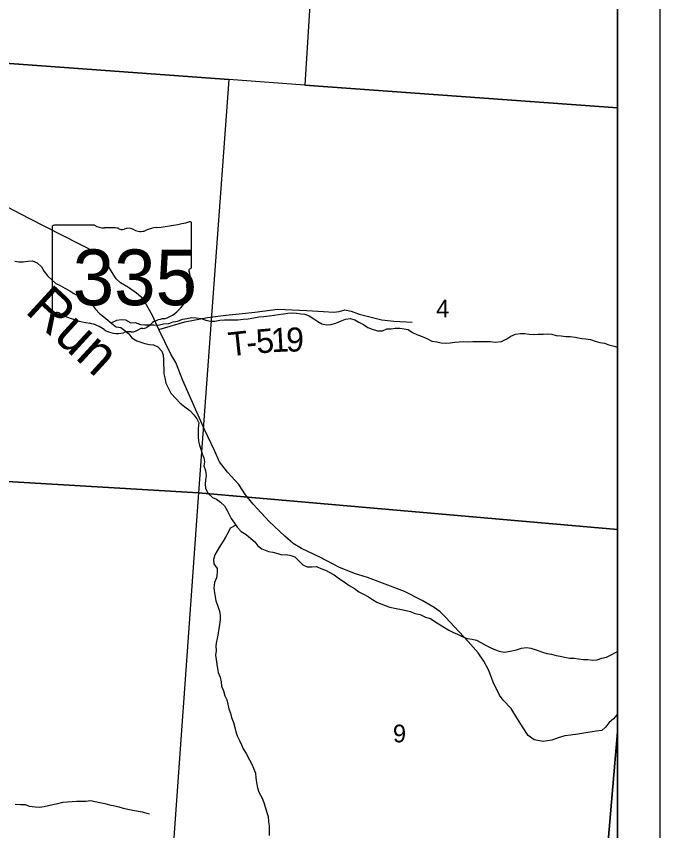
# Model space of a CAD drawing. Extents: x 0 to 34, y 0 to 22.
# Drawn here: x 29.394 to 30.917, y 15.21 to 17.138 of the extents above; entities that cross this region are included whole.
import ezdxf

# ---------------------------------------------------------------- set-up
doc = ezdxf.new("R2010")
doc.units = 0
for name, color, linetype in [('GM_X_County', 7, 'Continuous'), ('GM_X_Minor_River', 7, 'Continuous'), ('GM_X_Minor_River_Text', 7, 'Continuous'), ('GM_X_Section', 7, 'Continuous'), ('GM_X_Section_Text', 7, 'Continuous'), ('GM_X_State_Location', 7, 'Continuous'), ('GM_X_State_Route', 7, 'Continuous'), ('GM_X_State_Shield', 7, 'Continuous'), ('GM_X_Township', 7, 'Continuous'), ('GM_X_Township_Road', 7, 'Continuous'), ('GM_X_Township_Road_Text', 7, 'Continuous'), ('SH_Data', 7, 'Continuous')]:
    doc.layers.add(name, color=color, linetype=linetype)

msp = doc.modelspace()

# ---------------------------------------------------------------- linework, layer by layer
at = {"layer": 'GM_X_County'}
msp.add_lwpolyline([(24.0167, 20.4902), (24.0167, 14.1), (30.8167, 14.1), (30.8167, 19.9966)], dxfattribs=at)
at = {"layer": 'GM_X_Minor_River'}
for points in [[(29.3901, 16.5582), (29.3999, 16.5567), (29.4102, 16.5567), (29.4211, 16.5583), (29.4317, 16.559), (29.4431, 16.5541), (29.453, 16.5443), (29.4594, 16.5337), (29.4682, 16.5227), (29.4871, 16.5053), (29.4977, 16.5), (29.5084, 16.4943), (29.5205, 16.4879), (29.53, 16.4814), (29.5425, 16.4754), (29.552, 16.4686), (29.5626, 16.4621), (29.5736, 16.4538), (29.5808, 16.4443), (29.5903, 16.4341), (29.6005, 16.4265), (29.6104, 16.4186), (29.6199, 16.4102), (29.6301, 16.4023), (29.6407, 16.4008), (29.6502, 16.394), (29.66, 16.3856), (29.6673, 16.3762), (29.6786, 16.369), (29.6885, 16.3659), (29.698, 16.3633), (29.7086, 16.3607), (29.7184, 16.3599), (29.7286, 16.3554), (29.7378, 16.3448), (29.7416, 16.3353), (29.7423, 16.3251), (29.742, 16.314), (29.7428, 16.3023), (29.7432, 16.2913), (29.7451, 16.2818), (29.7474, 16.2693), (29.7531, 16.2579), (29.7595, 16.2454), (29.7713, 16.2329), (29.7808, 16.2223), (29.7926, 16.2132), (29.8047, 16.2041), (29.8142, 16.1943), (29.8206, 16.1848), (29.8256, 16.1753), (29.8245, 16.1624), (29.8245, 16.1423), (29.8253, 16.1321), (29.8276, 16.1226), (29.8306, 16.1131), (29.8337, 16.1021), (29.8379, 16.0926), (29.8394, 16.0828), (29.8375, 16.0733), (29.8413, 16.0623)], [(29.618, 16.4118), (29.6312, 16.4182), (29.6422, 16.4201), (29.652, 16.419), (29.6645, 16.4122), (29.6748, 16.4126), (29.6876, 16.4077), (29.6982, 16.4069), (29.7194, 16.407), (29.7293, 16.4066), (29.7418, 16.4097), (29.755, 16.4108), (29.7649, 16.4143), (29.7762, 16.4158), (29.7872, 16.4204), (29.7978, 16.4223), (29.8084, 16.4249), (29.8194, 16.4242), (29.8315, 16.4219), (29.8425, 16.4182), (29.8535, 16.4159), (29.8637, 16.4156), (29.8754, 16.4182), (29.8864, 16.419), (29.8966, 16.4194), (29.9072, 16.419), (29.9182, 16.4194), (29.9303, 16.4206), (29.9424, 16.4214), (29.9557, 16.4237), (29.9674, 16.4263), (29.9799, 16.4267), (29.992, 16.4287), (30.0037, 16.4302), (30.0143, 16.4317), (30.0265, 16.4329), (30.0367, 16.4352), (30.0469, 16.4356), (30.0571, 16.4352), (30.067, 16.4333), (30.0768, 16.4322), (30.087, 16.4284), (30.0977, 16.4216), (30.1071, 16.4152), (30.117, 16.4099), (30.1268, 16.4069), (30.1378, 16.408), (30.1503, 16.4115), (30.1613, 16.416), (30.173, 16.4206), (30.1851, 16.4221), (30.1946, 16.4191), (30.2048, 16.4138), (30.2158, 16.4081), (30.2257, 16.401), (30.2363, 16.3968), (30.2484, 16.3934), (30.2601, 16.3934), (30.2704, 16.398), (30.2806, 16.3976), (30.2908, 16.3995), (30.3014, 16.3996), (30.3116, 16.3981), (30.3215, 16.3966), (30.3313, 16.3894), (30.342, 16.3844), (30.3545, 16.3795), (30.3658, 16.3746), (30.3776, 16.3686), (30.3893, 16.3667), (30.3992, 16.3648), (30.409, 16.3637), (30.4207, 16.3648), (30.4313, 16.366), (30.4416, 16.3668), (30.4518, 16.3676), (30.4639, 16.3672), (30.4745, 16.368), (30.4855, 16.3676), (30.5037, 16.368), (30.5165, 16.3677), (30.5268, 16.3665), (30.5419, 16.3681), (30.5544, 16.3738), (30.5642, 16.3806), (30.5756, 16.3852), (30.5869, 16.3871), (30.5975, 16.3864), (30.6074, 16.3853), (30.6183, 16.3841), (30.6293, 16.3849), (30.6411, 16.3849), (30.6513, 16.3857), (30.6611, 16.385), (30.6714, 16.3823), (30.6835, 16.3816), (30.6948, 16.3797), (30.7047, 16.3793), (30.7168, 16.3782), (30.732, 16.3752), (30.7418, 16.3741)], [(30.7418, 16.3741), (30.7532, 16.3722), (30.7638, 16.3684), (30.7748, 16.3658), (30.7857, 16.3635), (30.796, 16.3598), (30.8092, 16.3571), (30.8167, 16.3545)], [(29.8413, 16.0623), (29.8429, 16.0501), (29.8418, 16.0403), (29.8407, 16.0304), (29.8414, 16.0205), (29.8471, 16.0088), (29.8578, 15.9989), (29.8676, 15.9944), (29.8771, 15.9872), (29.8866, 15.9785), (29.893, 15.9679), (29.8976, 15.958), (29.9022, 15.9485), (29.9101, 15.9375), (29.9166, 15.9281), (29.9261, 15.9178), (29.9375, 15.911), (29.9485, 15.9019), (29.9579, 15.894), (29.9655, 15.8845), (29.975, 15.8769), (29.9909, 15.8709), (30.0008, 15.8694), (30.0129, 15.8664), (30.0224, 15.863), (30.0334, 15.8638), (30.0432, 15.8611), (30.0527, 15.8585), (30.0625, 15.849), (30.072, 15.8395), (30.0819, 15.8342), (30.0925, 15.8346), (30.1042, 15.8354), (30.1145, 15.8309), (30.1254, 15.8267), (30.1357, 15.8214), (30.1463, 15.8157), (30.1584, 15.8063), (30.1698, 15.7987), (30.1819, 15.7904), (30.1941, 15.7832), (30.2043, 15.7756), (30.2157, 15.7699), (30.2271, 15.7635), (30.2369, 15.7575), (30.2468, 15.7506), (30.2566, 15.7472), (30.2669, 15.7427), (30.2775, 15.7389), (30.293, 15.7359), (30.3051, 15.7333), (30.3161, 15.7314), (30.3267, 15.7288), (30.3373, 15.7242), (30.3498, 15.7216), (30.3623, 15.7152), (30.3744, 15.7122), (30.387, 15.7034), (30.3968, 15.6974), (30.4074, 15.6906), (30.4173, 15.6845), (30.4283, 15.6792), (30.4381, 15.6747), (30.4487, 15.6694), (30.4605, 15.6649), (30.4726, 15.6634), (30.4832, 15.6611), (30.4935, 15.6554), (30.506, 15.6486), (30.5166, 15.6429), (30.5276, 15.638), (30.537, 15.6346), (30.5495, 15.6328), (30.5624, 15.6347), (30.5779, 15.6381), (30.5893, 15.6416), (30.6014, 15.6435), (30.6112, 15.6416), (30.6215, 15.6389), (30.6389, 15.6321), (30.6495, 15.6295), (30.6609, 15.6276), (30.6715, 15.6246), (30.6809, 15.6227), (30.6916, 15.6205), (30.7037, 15.6186), (30.7139, 15.6179), (30.7245, 15.6167), (30.7362, 15.6149), (30.7465, 15.6153), (30.7582, 15.6138), (30.7688, 15.6141), (30.7798, 15.6183), (30.7908, 15.6203), (30.8021, 15.626), (30.8134, 15.6321), (30.8167, 15.6341)], [(29.9129, 15.9334), (29.8996, 15.9258), (29.8954, 15.9155), (29.889, 15.9049), (29.8834, 15.895), (29.8762, 15.884), (29.869, 15.8726), (29.8634, 15.8631), (29.8607, 15.8521), (29.8615, 15.8415), (29.8691, 15.8309), (29.8691, 15.8199), (29.8676, 15.8088), (29.8631, 15.7975), (29.8616, 15.7849), (29.8628, 15.7732), (29.8647, 15.7637), (29.8662, 15.7542), (29.8704, 15.7417), (29.875, 15.7296), (29.8762, 15.7193), (29.8762, 15.7087), (29.8743, 15.6981), (29.8732, 15.6878), (29.8717, 15.6783), (29.8702, 15.6677), (29.8676, 15.6582), (29.8657, 15.6476), (29.8669, 15.6358), (29.865, 15.6256), (29.8665, 15.615), (29.8681, 15.6043), (29.87, 15.5937), (29.8712, 15.5842), (29.8761, 15.5736), (29.8784, 15.5622), (29.8792, 15.552), (29.8837, 15.5406), (29.8876, 15.5292), (29.8921, 15.5194), (29.894, 15.5095), (29.8971, 15.4985), (29.9009, 15.4883), (29.9032, 15.4777), (29.9078, 15.4663), (29.9108, 15.4538), (29.9131, 15.4443), (29.9162, 15.4348), (29.9222, 15.4234), (29.9264, 15.4128), (29.9306, 15.4033), (29.9374, 15.3927), (29.9454, 15.3776), (29.9508, 15.3673), (29.9553, 15.3578), (29.9595, 15.3461), (29.9607, 15.3351), (29.9622, 15.3241), (29.9645, 15.3112), (29.9676, 15.301), (29.9755, 15.2873), (29.9797, 15.2763), (29.9828, 15.2665), (29.987, 15.2532), (29.9896, 15.2433), (29.9908, 15.2312), (29.992, 15.2217), (29.992, 15.2103), (29.9924, 15.1985)], [(29.3906, 15.2727), (29.4035, 15.272), (29.4148, 15.272), (29.4243, 15.2682), (29.4379, 15.2663), (29.4489, 15.2656), (29.4599, 15.2671), (29.4701, 15.2694), (29.48, 15.2717), (29.4917, 15.2744), (29.5038, 15.2771), (29.5151, 15.2786), (29.5257, 15.279), (29.5363, 15.2798), (29.5477, 15.2802), (29.5579, 15.2802), (29.5689, 15.281), (29.5806, 15.2791), (29.5916, 15.2768), (29.6034, 15.2746), (29.6144, 15.2708), (29.6265, 15.2685), (29.6367, 15.2663), (29.6466, 15.2636), (29.6575, 15.261), (29.6693, 15.2587), (29.6818, 15.2565), (29.6916, 15.2542), (29.703, 15.2516), (29.7087, 15.2497)]]:
    msp.add_lwpolyline(points, dxfattribs=at)
at = {"layer": 'GM_X_Section'}
for p, q in [((30.8167, 16.9208), (30.8167, 17.9065)), ((30.8167, 15.9231), (30.8167, 16.9208)), ((30.8167, 15.4443), (30.8167, 15.9231)), ((30.8167, 14.8848), (30.8167, 15.4443))]:
    msp.add_line(p, q, dxfattribs=at)
for points in [[(29.1178, 18.0184), (30.1374, 17.9516), (30.0764, 16.9749), (29.8965, 16.988), (29.0528, 17.0493)], [(28.8721, 17.0617), (29.0528, 17.0493), (29.8965, 16.988), (29.8251, 16.0098), (28.8121, 16.0697)], [(28.8121, 16.0697), (29.8251, 16.0098), (29.7516, 14.9839), (28.7351, 15.051)]]:
    msp.add_lwpolyline(points, close=True, dxfattribs=at)
for points in [[(30.8167, 17.9065), (30.1374, 17.9516), (30.0764, 16.9749), (30.8167, 16.9208)], [(30.8167, 16.9208), (30.0764, 16.9749), (29.8965, 16.988), (29.8251, 16.0098), (30.8167, 15.9231)], [(30.8167, 15.9231), (29.8251, 16.0098), (29.7516, 14.9839), (30.7695, 14.8891), (30.8167, 15.4443)], [(30.8167, 15.4443), (30.7695, 14.8891), (30.8167, 14.8848)]]:
    msp.add_lwpolyline(points, dxfattribs=at)
at = {"layer": 'GM_X_State_Route'}
msp.add_lwpolyline([(30.8167, 15.4851), (30.8149, 15.4838), (30.8072, 15.4748), (30.7972, 15.4658), (30.788, 15.4549), (30.7795, 15.447), (30.7662, 15.4453), (30.7229, 15.4383), (30.7054, 15.4363), (30.6921, 15.4345), (30.6764, 15.4298), (30.6616, 15.424), (30.641, 15.4208), (30.6194, 15.4249), (30.6055, 15.435), (30.5933, 15.453), (30.5788, 15.4771), (30.565, 15.499), (30.5459, 15.5186), (30.5374, 15.5305), (30.5222, 15.5615), (30.512, 15.589), (30.5005, 15.6115), (30.4867, 15.6311), (30.4632, 15.658), (30.4093, 15.7157), (30.3973, 15.728), (30.383, 15.7385), (30.3544, 15.7548), (30.3125, 15.7759), (30.2733, 15.7913), (30.2253, 15.809), (30.1943, 15.819), (30.1573, 15.8339), (30.114, 15.8565), (30.0687, 15.878), (30.0492, 15.8893), (30.0289, 15.9071), (29.9922, 15.9414), (29.954, 15.9826), (29.9365, 16.0048), (29.9201, 16.029), (29.8935, 16.0582), (29.8749, 16.0828), (29.8627, 16.1096), (29.8395, 16.1596), (29.7875, 16.2755), (29.771, 16.3179), (29.7591, 16.3381), (29.7307, 16.3963), (29.7163, 16.4291), (29.7059, 16.4475), (29.6937, 16.469), (29.6783, 16.4825), (29.6592, 16.496), (29.6399, 16.5066), (29.6298, 16.5158), (29.6209, 16.5311), (29.6109, 16.5468), (29.6042, 16.5587), (29.5945, 16.5714), (29.5836, 16.578), (29.4237, 16.6588), (29.354, 16.6951)], dxfattribs=at)
at = {"layer": 'GM_X_State_Shield'}
for p, q in [((29.4788, 16.6397), (29.4788, 16.4396)), ((29.5786, 16.6431), (29.4821, 16.6431)), ((29.8084, 16.5434), (29.8084, 16.6481)), ((29.8084, 16.5434), (29.8084, 16.5434))]:
    msp.add_line(p, q, dxfattribs=at)
for centre, major_axis, start_param, end_param in [((29.4826, 16.6401), (0.00382, 0), 1.712693, 3.28349), ((29.6016, 16.6664), (0.037, 0), 4.042523, 4.731795), ((29.6138, 16.5308), (0.133, 0), 1.404758, 1.657858), ((29.6597, 16.618), (0.0222, 0), 0.950623, 2.079405), ((29.7356, 16.582), (0.0703, 0), 1.699011, 2.107814), ((29.691, 16.916), (0.3495, 0), 4.814394, 5.042369), ((29.8047, 16.6485), (0.00367, 0), 6.141152, 7.989035), ((29.644, 16.6411), (0.0107, 0), 3.836095, 5.185415), ((29.6884, 16.6497), (0.0267, 0), 4.081561, 5.145723), ((29.8076, 16.5357), (0.00568, 0), 1.883978, 3.671073), ((29.8045, 16.543), (0.00393, 0), 5.05454, 6.418171), ((29.7714, 16.5225), (0.0341, 0), 5.934695, 6.695948), ((29.8215, 16.4996), (0.0248, 0), 2.387724, 3.262537), ((29.7106, 16.4863), (0.0874, 0), 5.101752, 6.440018), ((29.4826, 16.4391), (0.00385, 0), 3.00124, 4.508301), ((29.4832, 16.4596), (0.0294, 0), 4.665946, 4.897461), ((29.4892, 16.428), (0.0106, 0), 0.519207, 1.627899), ((29.623, 16.6078), (0.2524, 0), 4.195997, 4.488961), ((29.5478, 16.3497), (0.079, 0), 0.823519, 1.323587), ((29.6868, 16.4202), (0.0282, 0), 4.937069, 5.64225), ((29.7474, 16.3834), (0.0479, 0), 1.647645, 2.488434), ((29.6332, 16.427), (0.0501, 0), 4.026481, 4.996735), ((29.6622, 16.3578), (0.0412, 0), 1.495662, 1.94098), ((29.6658, 16.412), (0.0267, 0), 4.691044, 5.507374), ((29.69, 16.3927), (0.00752, 0), 1.147584, 2.315152)]:
    msp.add_ellipse(centre, major_axis=major_axis, ratio=0.8, start_param=start_param, end_param=end_param, dxfattribs=at)
at = {"layer": 'GM_X_Township'}
msp.add_lwpolyline([(27.704, 14.1), (30.8167, 14.1), (30.8167, 19.9966)], dxfattribs=at)
at = {"layer": 'GM_X_Township_Road'}
msp.add_lwpolyline([(29.7307, 16.3963), (29.7927, 16.4141), (29.8459, 16.4249), (29.8899, 16.4305), (29.929, 16.4337), (29.9586, 16.4371), (30.0125, 16.4441), (30.0816, 16.4415), (30.1207, 16.4391), (30.1449, 16.4375), (30.1575, 16.439), (30.1711, 16.4431), (30.1863, 16.4396), (30.2049, 16.4324), (30.2591, 16.4189), (30.2872, 16.4161), (30.3306, 16.4137)], dxfattribs=at)
at = {"layer": 'SH_Data'}
for points in [[(23.9167, 21), (30.9167, 21), (30.9167, 14), (23.9167, 14)], [(24.0167, 20.9), (30.8167, 20.9), (30.8167, 14.1), (24.0167, 14.1)]]:
    msp.add_lwpolyline(points, close=True, dxfattribs=at)

# ---------------------------------------------------------------- texts
at = {"layer": 'GM_X_Minor_River_Text'}
msp.add_text('Run', height=0.0947, rotation=317.4572, dxfattribs=at).set_placement((29.4117, 16.4379))
at = {"layer": 'GM_X_Section_Text'}
for s, p in [('4', (30.3876, 16.4251)), ('9', (30.2851, 15.419))]:
    msp.add_text(s, height=0.0419, rotation=0, dxfattribs=at).set_placement(p)
at = {"layer": 'GM_X_State_Location'}
for s in ['s', 'r']:
    msp.add_text(s, height=0.000189, dxfattribs=at).set_placement((29.6399, 16.5263))
msp.add_text('335', height=0.000189, rotation=0, dxfattribs=at).set_placement((29.573, 16.5125))
at = {"layer": 'GM_X_State_Shield'}
msp.add_text('335', height=0.13184, dxfattribs=at).set_placement((29.5272, 16.4537))
at = {"layer": 'GM_X_Township_Road_Text'}
for s, rotation, p in [('T', 6.1268, (29.8984, 16.3324)), ('5', 4.908, (29.9636, 16.3392)), ('1', 3.129, (29.998, 16.3422)), ('9', 359.6357, (30.032, 16.3441)), ('-', 5.8488, (29.9406, 16.3369))]:
    msp.add_text(s, height=0.0568, rotation=rotation, dxfattribs=at).set_placement(p)

doc.saveas('drawing.dxf')
